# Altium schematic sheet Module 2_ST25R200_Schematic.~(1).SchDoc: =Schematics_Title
size A4; PageSetup: Record=PageOptions¦CenterHorizontal=True¦CenterVertical=True¦PrintScale=0.97¦XCorrection=1.00¦YCorrection=1.00¦PrintKind=0¦BorderSize=5000000¦LeftOffset=0¦BottomOffset=0¦Orientation=2¦PaperLength=1000¦PaperWidth=1000¦Scale=100¦PaperSource=7¦PrintQuality=-4¦MediaType=1¦DitherType=10¦PaperKind=A4¦PrintScaleMode=1; SheetNumber: 4; SheetTotal: 5
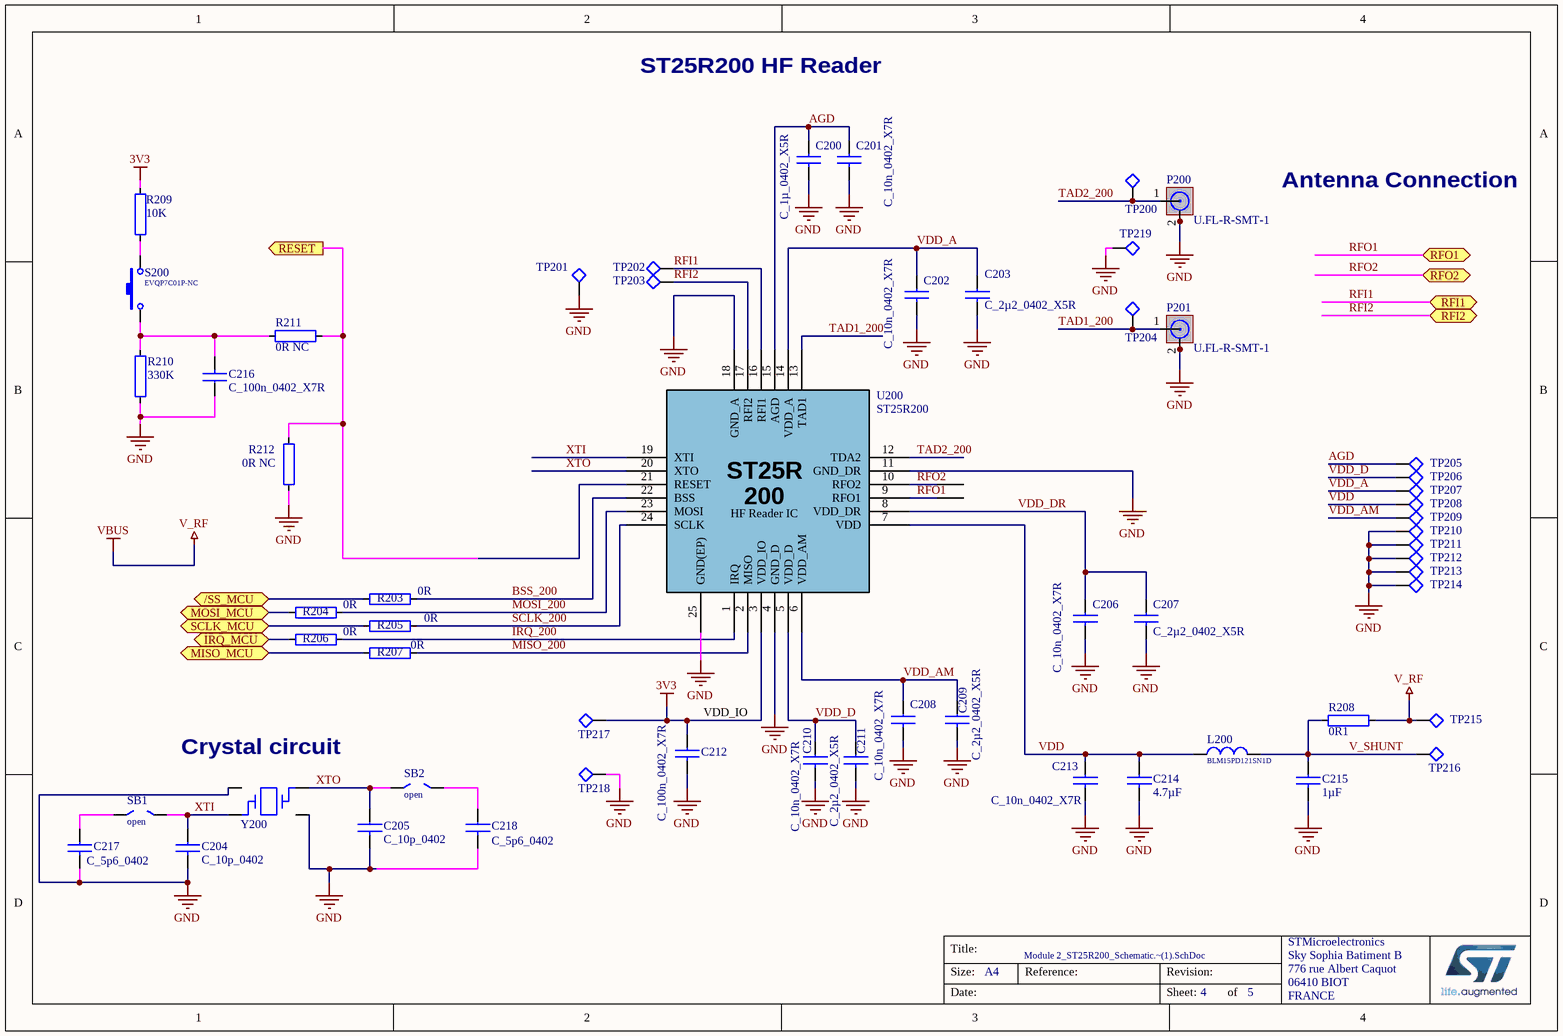
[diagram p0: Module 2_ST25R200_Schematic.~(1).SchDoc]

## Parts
C200  C_1µ_0402_X5R  [C0402]
C201  C_10n_0402_X7R  [C0402]
C202  C_10n_0402_X7R  [C0402]
C203  C_2µ2_0402_X5R  [C0402]
C204  C_10p_0402  [C0402]
C205  C_10p_0402  [C0402]
C206  C_10n_0402_X7R  [C0402]
C207  C_2µ2_0402_X5R  [C0402]
C208  C_10n_0402_X7R  [C0402]
C209  C_2µ2_0402_X5R  [C0402]
C210  C_10n_0402_X7R  [C0402]
C211  C_2µ2_0402_X5R  [C0402]
C212  C_100n_0402_X7R  [C0402]
C213  C_10n_0402_X7R  [C0402]
C214  4.7µF  [C0402]
C215  1µF  [C0402]
C216  C_100n_0402_X7R  [C0402]
C217  C_5p6_0402  [C0402]
C218  C_5p6_0402  [C0402]
L200  BLM15PD121SN1D  [L0402]
P200  U.FL-R-SMT-1  [U FL Socket - HRS - Surface Mount]
P201  U.FL-R-SMT-1  [U FL Socket - HRS - Surface Mount]
R203  0R  [R0402]
R204  0R  [R0402]
R205  0R  [R0402]
R206  0R  [R0402]
R207  0R  [R0402]
R208  0R1  [R0603]
R209  10K  [R0402]
R210  330K  [R0402]
R211  0R NC  [R0402]
R212  0R NC  [R0402]
S200  EVQP7C01P-NC  [PANASONIC-SWITCH-EVQP7C/EVQP7L]
SB1  open  [solder-bridge-0402]  (no BOM)
SB2  open  [solder-bridge-0402]  (no BOM)
TP200  (no value)  [1*1P_MALE]  (no BOM)
TP201  Test point percage 1mm-pad-carree  [1*1P_MALE]  (value not drawn)  (no BOM)
TP202  Test point percage 1mm-pad-carree  [1*1P_MALE]  (value not drawn)  (no BOM)
TP203  Test point percage 1mm-pad-carree  [1*1P_MALE]  (value not drawn)  (no BOM)
TP204  (no value)  [1*1P_MALE]  (no BOM)
TP205  Test point percage 1mm  [1*1P_MALE round]  (value not drawn)  (no BOM)
TP206  Test point percage 1mm  [1*1P_MALE round]  (value not drawn)  (no BOM)
TP207  Test point percage 1mm  [1*1P_MALE round]  (value not drawn)  (no BOM)
TP208  Test point percage 1mm  [1*1P_MALE round]  (value not drawn)  (no BOM)
TP209  Test point percage 1mm  [1*1P_MALE round]  (value not drawn)  (no BOM)
TP210  Test point percage 1mm  [1*1P_MALE round]  (value not drawn)  (no BOM)
TP211  Test point percage 1mm  [1*1P_MALE round]  (value not drawn)  (no BOM)
TP212  Test point percage 1mm  [1*1P_MALE round]  (value not drawn)  (no BOM)
TP213  Test point percage 1mm  [1*1P_MALE round]  (value not drawn)  (no BOM)
TP214  Test point percage 1mm  [1*1P_MALE round]  (value not drawn)  (no BOM)
TP215  Test point percage 1mm  [1*1P_MALE round]  (value not drawn)  (no BOM)
TP216  Test point percage 1mm  [1*1P_MALE round]  (value not drawn)  (no BOM)
TP217  Test point percage 1mm  [1*1P_MALE round]  (value not drawn)  (no BOM)
TP218  Test point percage 1mm  [1*1P_MALE round]  (value not drawn)  (no BOM)
TP219  (no value)  [1*1P_MALE]  (no BOM)
U200  ST25R200  [ST25R200 QFN]
Y200  NDK 27,12MHz Crystal  [XRCGB_F_MN]  (value not drawn)

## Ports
/SS_MCU (bidir), IRQ_MCU (bidir), MISO_MCU (bidir), MOSI_MCU (bidir), RESET (out), RFI1 (bidir), RFI2 (bidir), RFO1 (bidir), RFO2 (bidir), SCLK_MCU (bidir)

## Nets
3V3: C212.1 R209.2 TP217.1 U200.3(VDD_IO)
GND: C200.2 C201.2 C202.2 C203.2 C204.2 C205.2 C206.2 C207.2 C208.2 C209.2 C210.2 C211.2 C212.2 C213.2 C214.2 C215.2 C216.1 C217.2 C218.2 P200.2 P200.3 P201.2 P201.3 R210.1 R212.2 TP201.1 TP210.1 TP211.1 TP212.1 TP213.1 TP214.1 TP218.1 TP219.1 U200.4(GND_D) U200.11(GND_DR) U200.18(GND_A) U200.25(GND(EP)) Y200.2 Y200.4
V_RF: R208.2 TP215.1  [also labelled VBUS]
/SS_MCU: R203.1 ; port /SS_MCU
AGD: C200.1 C201.1 TP205.1 U200.15(AGD)
BSS_200: R203.2 U200.22(BSS)
IRQ_200: R206.2 U200.1(IRQ)
IRQ_MCU: R206.1 ; port IRQ_MCU
MISO_200: R207.2 U200.2(MISO)
MISO_MCU: R207.1 ; port MISO_MCU
MOSI_200: R204.2 U200.23(MOSI)
MOSI_MCU: R204.1 ; port MOSI_MCU
RESET: R211.1 R212.1 U200.21(RESET) ; port RESET
RFI1: TP202.1 U200.16(RFI1) ; port RFI1
RFI2: TP203.1 U200.17(RFI2) ; port RFI2
RFO1: U200.9(RFO1) ; port RFO1
RFO2: U200.10(RFO2) ; port RFO2
SCLK_200: R205.2 U200.24(SCLK)
SCLK_MCU: R205.1 ; port SCLK_MCU
TAD1_200: P201.1 TP204.1 U200.13(TAD1)
TAD2_200: P200.1 TP200.1 U200.12(TDA2)
V_SHUNT: C215.1 L200.1 R208.1 TP216.1
VDD: C213.1 C214.1 L200.2 TP208.1 U200.7(VDD)
VDD_A: C202.1 C203.1 TP207.1 U200.14(VDD_A)
VDD_AM: C208.1 C209.1 TP209.1 U200.6(VDD_AM)
VDD_D: C210.1 C211.1 TP206.1 U200.5(VDD_D)
VDD_DR: C206.1 C207.1 U200.8(VDD_DR)
XTI: C204.1 SB1.2 U200.19(XTI) Y200.3
XTO: C205.1 SB2.1 U200.20(XTO) Y200.1
NetC216_2: C216.2 R210.2 R211.2 S200.1
NetC217_1: C217.1 SB1.1
NetC218_1: C218.1 SB2.2
NetR209_1: R209.1 S200.2

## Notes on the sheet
- ST25R200 HF Reader
- Antenna Connection
- (near C212) VDD_IO
- (near Y200) Crystal circuit

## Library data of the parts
C200 C215 = C_1µ_0402_X5R: 1u_X5R; Manufacturer: MURATA; Manufacturer Part Number: GRM155R61C105KA12D; 2nd Source: 0402, 1 µF, 16 V, ± 10%, X5R,; PickPlace: Yes
C201 C202 C206 C208 C210 C213 = C_10n_0402_X7R: 10n_x7R; Manufacturer: AVX; Manufacturer Part Number: 04023C103KAT2A; 2nd Source: 0402, 0.01 µF, 25 V, ± 10%, X7R; PickPlace: Yes
C203 C207 C209 C211 = C_2µ2_0402_X5R: 2u2_X5R; Manufacturer: MURATA; Manufacturer Part Number: GRM155R60J225ME15D; 2nd Source: 0402, 2.2 µF, 6.3 V, ± 20%, X5R; PickPlace: Yes
C204 C205 = C_10p_0402: 10p_C0G; Manufacturer: MURATA; Manufacturer Part Number: GRM1555C1H100GA01D; 2nd Source: 0402, 0.01 µF, 25 V, ± 10%, X7R; PickPlace: Yes
C212 C216 = C_100n_0402_X7R: 100n_x7R 0402; Manufacturer: MULTICOMP; Manufacturer Part Number: MC0402X104K100CT; 2nd Source: 0402, 0.1 µF, 10 V, ± 10%, X7R; PickPlace: Yes
C214 = C_4µ7_0402_X5R_10V: 4u7_X5R_10V_0402; Manufacturer: MURATA; Manufacturer Part Number: GRM155R61A475MEAA; PickPlace: Yes
C217 C218 = C_10p_0402: 5P6_C0G; Manufacturer: MURATA; Manufacturer Part Number: GRM1555C1H5R6BA01D; PickPlace: Yes
L200 = BLM15PD121SN1D: FERRITE BEAD; Manufacturer: MURATA; PickPlace: Yes
P200 P201 = U.FL-R-SMT-1: Manufacturer: HIROSE(HRS); Manufacturer Part Number: U.FL-R-SMT-1(10); 2nd Source: yes
R203-R207 = R0402_0R: 0R, 0402; Manufacturer: MULTI-SOURCES; Manufacturer Part Number: RESISTOR 0402 0R 62mW; 2nd Source: 0 ohm, 50 V, 0402, >62.5 mW; PickPlace: Yes
R208 = R0603_0R1: 0R1, 0603; Manufacturer: OHMITE; Manufacturer Part Number: KDV06DR100ET; PickPlace: Yes
R209 = R0402_10K: 10K, 0402; Manufacturer: MULTI-SOURCES; Manufacturer Part Number: 0402 10K 1%; PickPlace: Yes
R210 = R0402_330K: 330K, 0402; Manufacturer: MULTI-SOURCES; Manufacturer Part Number: 0402 330K 1%; PickPlace: Yes
R211 R212 = R0402_0R_NC: 0R, 0402 NOT FITTED; Manufacturer: MULTICOMP; Manufacturer Part Number: MC00625W040210R NOT FITTED; 2nd Source: 0 ohm, 50 V, 0402, >62.5 mW NOT FITTED; PickPlace: Yes
S200 = EVQP7C01P-NC: SIDE SWITCH NOT FITTED; Manufacturer: PANASONIC; Manufacturer Part Number: EVQP7C01P NOT FITTED; PickPlace: Yes
SB1 SB2 = solder_jumper_open_0402
TP200-TP204 TP219 = Test point percage 1mm-pad-carree: Part Number: Test point 0.5mm; PickPlace: No
TP205 TP206 TP208-TP218 = Test point percage 1mm: Part Number: Test point 0.5mm; Value: d.n.p.; PickPlace: No
TP207 = Test point percage 1mm: Part Number: Test point 0.5mm; PickPlace: No
U200 = ST25R200: HF READER ST25R200 QFN24; Manufacturer: ST MICRO; PickPlace: Yes
Y200 = NDK NX2016SA: NDK NX2016SA 27.12MHz; Manufacturer Part Number: NX2016SA STD-CZS-5 27.12MHz; 2nd Source: Murata XRCGB27M120F3M00R0; PickPlace: Yes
